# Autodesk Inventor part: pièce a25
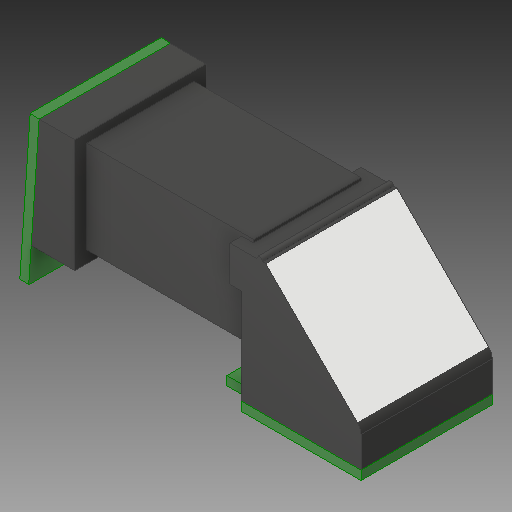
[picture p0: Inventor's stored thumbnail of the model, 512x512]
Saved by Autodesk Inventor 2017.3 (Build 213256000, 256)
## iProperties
Created: 2007-12
Part Number: pièce a25
Material: solidworks materials|PVC 0.007 plastifié|45
Document SubType Name: Modeling
Designer: ficho
Density: 1.29 g/cm^3
Appearance: 0,0,0
Author: ficho
Sending System: SolidWorks 2009
Last Author: christophe
Last Saved: 2011-02-10
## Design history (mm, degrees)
extrude "Extrusion4"
extrude "Extrusion13"
extrude "Congé1"
node "Solide1"
node "Solide2"
node "Solide3"
